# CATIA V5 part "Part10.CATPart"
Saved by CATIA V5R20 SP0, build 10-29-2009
Part number: Part10
Bounding box of the stored display mesh (mm): x -490 to 300, y 0 to 1500, z -220 to 430
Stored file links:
  E:\新建文件夹 (2)\Part10.CATPart
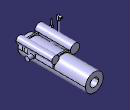
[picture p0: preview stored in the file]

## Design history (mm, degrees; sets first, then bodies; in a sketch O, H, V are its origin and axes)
Body1 (main body)
  Sketch1 on zx-plane, origin (0, 0, 0), H (-1, 0, 0), V (0, 0, 1)
    circle A1 centre (0, 0) radius 200
    point P1 (0, 200)
    radius A1 = 200
    coincidence: A1 P1, P1 V
  Pad1: profile Sketch1, direction (0, 1, 0), length 1500
  Sketch2 on yz-plane, origin (0, 0, 0), H (0, 1, 0), V (0, 0, 1)
    circle A1 centre (300, 0) radius 50
    point P1 (300, 0)
    radius A1 = 50
    coincidence: P1 H
  Pad2: profile Sketch2, direction (1, 0, 0), length 300, mirrored extent
  Plane1: type Offset, RefPlane zx-plane, Offset 100
  Sketch3 on Plane1, origin (0, 100, 0), H (-1, 0, 0), V (0, 0, 1)
    line L1 (-200, 220) -> (200, 220)
    point P1 (0, 200)
    point P2 (0, 200)
    point P3 (-200, 0)
    point P4 (200, 0)
    line L2 (200, 0) -> (-200, 0)
    point P5 (200, 0)
    line L3 (-200, 0) -> (-200, 220)
    line L4 (200, 0) -> (200, 220)
    horizontal: L1 H, L2 H
    coincidence: P1 V, P2 V, P3 H, P4 H, P5 H
    vertical: L3 V, L4 V
  Pad3: profile Sketch3, direction (0, 1, 0), length 30
  Plane2: type Offset, RefPlane zx-plane, Offset 800
  Sketch4 on Plane2, origin (0, 800, 0), H (-1, 0, 0), V (0, 0, 1)
    point P1 (0, 110)
    line L1 (200, 220) -> (200, 0)
    line L2 (200, 0) -> (-200, 0)
    line L3 (-200, 0) -> (-200, 220)
    line L4 (-200, 220) -> (200, 220)
    coincidence: P1 V
    vertical: L1 V, L3 V
    horizontal: L2 H, L4 H
    equidistance: L1 L3 P1, L2 L4 P1
  Pad4: profile Sketch4, direction (0, -1, 0), length 30
  Sketch5 on start face of Pad3, origin (0, 100, 0), H (1, 0, 0), V (0, 0, 1)
    circle A1 centre (220, 220) radius 80
    circle A2 centre (-220, 220) radius 100
  Pad5: profile Sketch5, direction (0, 1, 0), length 750, opposite side length 50
  Body2
    Sketch6 on zx-plane, origin (0, 0, 0), H (-1, 0, 0), V (0, 0, 1)
      circle A1 centre (-220, 220) radius 30
      point P3 (-192.1457, 208.8583)
      circle A2 centre (220, 220) radius 30
      point P4 (192.1457, 208.8583)
      radius A2 = 30
      radius A1 = 30
      coincidence: A1 P3, A2 P4
    Pad6: profile Sketch6, direction (0, 1, 0), length 700
  Remove1: tool Body2
  Body3
    Sketch7 on zx-plane, origin (0, 0, 0), H (-1, 0, 0), V (0, 0, 1)
      circle A1 centre (0, 0) radius 92.1954
      radius A1 = 92.1954
    Pad7: profile Sketch7, direction (0, 1, 0), length 1500
  Remove2: tool Body3
  Sketch8 on start face of Pad2, origin (-300, 0, 0), H (0, -1, 0), V (0, 0, 1)
    point P1 (-420, 0)
    line L1 (-410, 50) -> (-410, -50)
    line L2 (-410, -50) -> (-430, -50)
    line L3 (-430, -50) -> (-430, 50)
    line L4 (-430, 50) -> (-410, 50)
    coincidence: P1 H
    vertical: L1 V, L3 V
    horizontal: L2 H, L4 H
    equidistance: L1 L3 P1, L2 L4 P1
  Pad8: profile Sketch8, direction (1, 0, 0), length 120, opposite side length 60
  Sketch9 on start face of Pad8, origin (-360, 0, 0), H (0, -1, 0), V (0, 0, 1)
    point P1 (-420, 0)
    line L1 (-410, -50) -> (-430, -50)
    line L2 (-430, -50) -> (-430, 50)
    line L3 (-430, 50) -> (-410, 50)
    line L4 (-410, -50) -> (-190, 120)
    line L5 (-190, 120) -> (-190, 220)
    line L6 (-190, 220) -> (-410, 50)
    coincidence: P1 H
    horizontal: L1 H, L3 H
    vertical: L2 V
    equidistance: L1 L3 P1
    parallelism: L6 L4
  Pad9: profile Sketch9, direction (-1, 0, 0), length 20
  Sketch10 on face of Pad9 from Sketch9.L5, origin (0, 190, 0), H (1, 0, 0), V (0, 0, 1)
    point P1 (-370, 170)
    line L1 (-350, 260) -> (-350, 80)
    line L2 (-350, 80) -> (-390, 80)
    line L3 (-390, 80) -> (-390, 260)
    line L4 (-390, 260) -> (-350, 260)
    vertical: L1 V, L3 V
    horizontal: L2 H, L4 H
    equidistance: L1 L3 P1, L2 L4 P1
  Pad10: profile Sketch10, direction (0, -1, 0), length 40
  Sketch11 on face of Pad10 from Sketch10.L2, origin (0, 0, 80), H (1, 0, 0), V (0, -1, 0)
    circle A1 centre (-370, -170) radius 10
  Pad11: profile Sketch11, direction (0, 0, -1), length 300, mirrored extent
  Sketch12 on face of Pad10 from Sketch10.L2, origin (0, 0, 80), H (1, 0, 0), V (0, -1, 0)
    point P1 (-370, -170)
    line L1 (-350, -150) -> (-350, -190)
    line L2 (-350, -190) -> (-390, -190)
    line L3 (-390, -190) -> (-390, -150)
    line L4 (-390, -150) -> (-350, -150)
    vertical: L1 V, L3 V
    horizontal: L2 H, L4 H
    equidistance: L1 L3 P1, L2 L4 P1
  Pad12: profile Sketch12, direction (0, 0, -1), length 150, opposite side length -100
  Sketch13 on face of Pad12 from Sketch12.L3, origin (-390, 0, 0), H (0, -1, 0), V (0, 0, 1)
    point P1 (-170, -40)
    line L1 (-150, -20) -> (-150, -60)
    line L2 (-150, -60) -> (-190, -60)
    line L3 (-190, -60) -> (-190, -20)
    line L4 (-190, -20) -> (-150, -20)
    vertical: L1 V, L3 V
    horizontal: L2 H, L4 H
    equidistance: L1 L3 P1, L2 L4 P1
  Pad13: profile Sketch13, direction (-1, 0, 0), length 100
  Sketch14 on face of Pad13, origin (0, 150, 0), H (1, 0, 0), V (0, 0, 1)
    point P1 (-470, -40)
    line L1 (-450, -20) -> (-450, -60)
    line L2 (-450, -60) -> (-490, -60)
    line L3 (-490, -60) -> (-490, -20)
    line L4 (-490, -20) -> (-450, -20)
    vertical: L1 V, L3 V
    horizontal: L2 H, L4 H
    equidistance: L1 L3 P1, L2 L4 P1
  Pad14: profile Sketch14, direction (0, -1, 0), length 20, opposite side length 100
  Sketch15 on face of Pad13, origin (0, 0, -20), H (1, 0, 0), V (0, 1, 0)
    circle A1 centre (-470, 230) radius 20
  Pad15: profile Sketch15, direction (0, 0, 1), length 350, opposite side length 40
  Sketch16 on end face of Pad15, origin (0, 0, 330), H (1, 0, 0), V (0, 1, 0)
    point P1 (-470, 230)
    line L1 (-450, 250) -> (-450, 210)
    line L2 (-450, 210) -> (-490, 210)
    line L3 (-490, 210) -> (-490, 250)
    line L4 (-490, 250) -> (-450, 250)
    vertical: L1 V, L3 V
    horizontal: L2 H, L4 H
    equidistance: L1 L3 P1, L2 L4 P1
  Pad16: profile Sketch16, direction (0, 0, 1), length 100
  Sketch17 on face of Pad16 from Sketch16.L4, origin (0, 250, 0), H (-1, 0, 0), V (0, 0, 1)
    circle A1 centre (470, 410) radius 20
  Pad17: profile Sketch17, direction (0, 1, 0), length 50
  Sketch18 on end face of Pad17, origin (0, 300, 0), H (-1, 0, 0), V (0, 0, 1)
    circle A1 centre (470, 410) radius 14.1421
    point P1 (470, 410)
    point P2 (484.1421, 410)
    point P3 (470, 410)
    coincidence: P2 A1, P3 P1
  Plane3: type Normal, Curve Sketch18.A1, RefPoint Sketch18.P2
  Sketch19 on Plane3, origin (0, 0, 410), H (1, 0, 0), V (0, 1, 0)
    circle A1 centre (-484.1421, 300) radius 3
    point P1 (-484.1421, 300)
    reference projected point E1 (-484.1421, 300) from Sketch18.P2
    coincidence: P1 E1
  Sketch20 on face of Pad16 from Sketch16.L2, origin (0, 210, 0), H (1, 0, 0), V (0, 0, 1)
    point P1 (-470, 410)
  Line1: type PtPt, FirstPoint Sketch20, SecondPoint Sketch18.P3
  Shaft1: profile Sketch19, axis Line1, angle 360
  Sketch21 on end face of Pad14, origin (0, 130, 0), H (1, 0, 0), V (0, 0, 1)
    circle A1 centre (-470, -40) radius 20
    circle A2 centre (-470, -40) radius 14.1421
  Pad18: profile Sketch21, direction (0, -1, 0), length 30
  Sketch22 on face of Pad4 from Sketch4.L3, origin (200, 0, 0), H (0, 1, 0), V (0, 0, 1)
    point P1 (380, 0)
    line L1 (380, 0) -> (210, 0)
    line L2 (210, 0) -> (210, 97.5668)
    line L3 (210, 97.5668) -> (380, 97.5668)
    line L4 (380, 97.5668) -> (380, 0)
    coincidence: P1 H
    horizontal: L1 H, L3 H
    vertical: L2 V, L4 V
  Pad19: profile Sketch22, direction (-1, 0, 0), length 30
